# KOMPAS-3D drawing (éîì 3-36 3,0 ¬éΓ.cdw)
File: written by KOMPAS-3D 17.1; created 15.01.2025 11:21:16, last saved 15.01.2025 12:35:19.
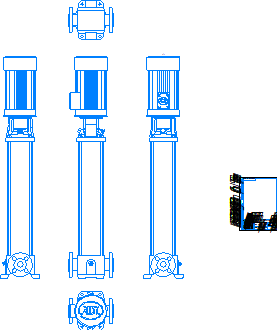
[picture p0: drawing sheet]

Sheet 1: A4, portrait

Title block, sheet 1: name: ВМН 3-36 3,0 кВт; designation: ВМН 3-36 3,0 кВт; material: Сталь 10  ГОСТ 1050-2013; mass: 68,16; sheets: 1; sheet format: A4; stored path: \\adlc.lan\data\АДЛ_ПКД\3D-модели\ADL production\Насосы ГРАНПАМП\Насосы ВМН\ВМН3\KOMPAS 3D\ВМН 3-36 3,0 кВт.cdw

Views: Проекционный вид 2, Проекционный вид 3, Проекционный вид 4, Проекционный вид 5
Referenced files in \\adlc.lan\data\АДЛ_ПКД\3D-модели\ADL production\Насосы ГРАНПАМП\Насосы ВМН\ВМН3\KOMPAS 3D\: ВМН 3-36 3,0 кВт.m3d
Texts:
  Andrey
  АДЛ
Dimensions and other numbers on the sheet: 1:1; 1; 68,16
